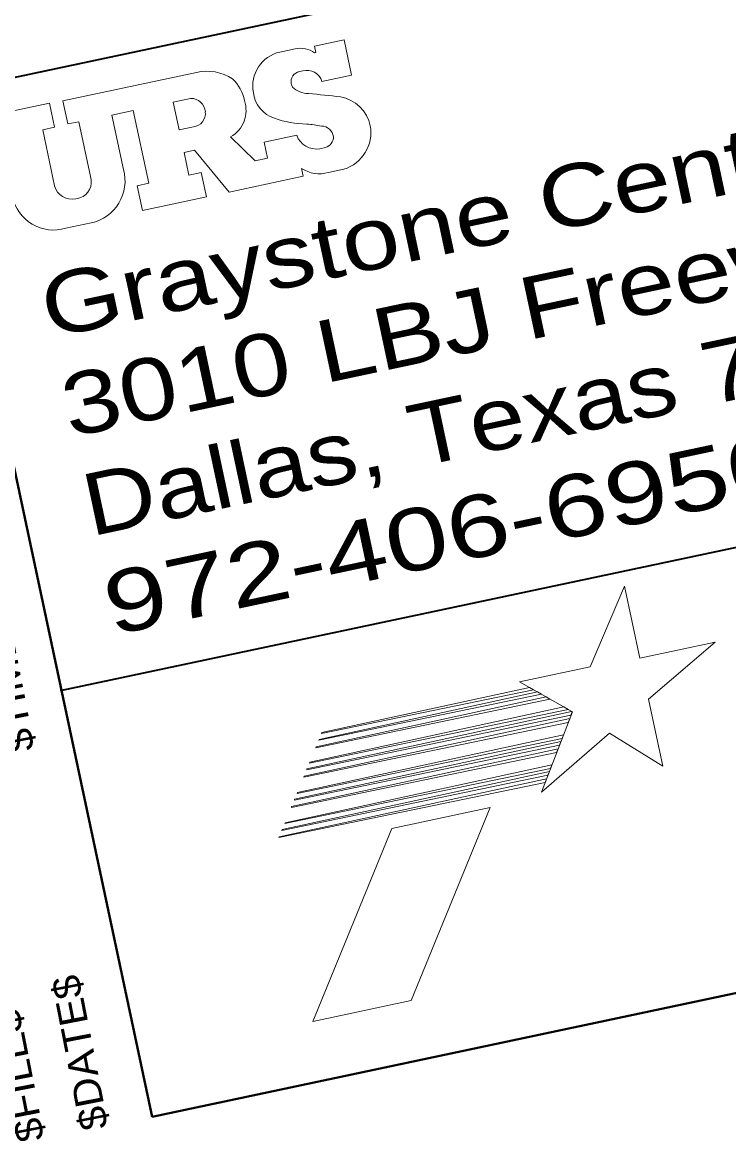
# Model space of a CAD drawing. Extents: x 2357218 to 2371708, y 6973728 to 6980157.
# Drawn here: x 2358089.1 to 2358239.3, y 6973921.3 to 6974159.6 of the extents above; entities that cross this region are included whole.
import ezdxf

# ---------------------------------------------------------------- set-up
doc = ezdxf.new("R2010")
doc.units = 0
doc.header["$LTSCALE"] = 2
for name, color, linetype, lineweight in [('44', 7, 'Continuous', 13), ('62', 7, 'Continuous', 13), ('63', 7, 'Continuous', 13)]:
    doc.layers.add(name, color=color, linetype=linetype, lineweight=lineweight)
doc.layers.add('60', color=7, linetype='Continuous')

msp = doc.modelspace()

# ---------------------------------------------------------------- linework, layer by layer
at = {"layer": '44', "lineweight": 40}
msp.add_lwpolyline([(2358116.692, 6973926.537), (2357409.76, 6977252.388), (2370517.53, 6980038.532)], dxfattribs=at)
at = {"layer": '62', "lineweight": 40}
msp.add_line((2371224.464, 6976712.679), (2358116.692, 6973926.537), dxfattribs=at)
at = {"layer": '62', "lineweight": 35}
for p, q in [((2358706.979, 6974279.557), (2358070.155, 6974144.195)), ((2358484.341, 6974099.558), (2358097.137, 6974017.255))]:
    msp.add_line(p, q, dxfattribs=at)
at = {"layer": '62'}
for p, q in [((2358143.877, 6974153.276), (2358147.138, 6974153.969)), ((2358148.729, 6974149.271), (2358148.058, 6974149.129)), ((2358121.18, 6974142.621), (2358124.862, 6974143.404)), ((2358152.367, 6974132.696), (2358153.533, 6974132.985)), ((2358157.428, 6974128.323), (2358154.166, 6974127.63)), ((2358100.481, 6974122.05), (2358101.323, 6974122.229)), ((2358103.731, 6974116.906), (2358098.3, 6974115.755))]:
    msp.add_line(p, q, dxfattribs=at)
for points in [[(2358151.251, 6974153.118), (2358151.487, 6974153.168), (2358151.203, 6974154.504), (2358157.516, 6974155.845), (2358159.104, 6974148.372), (2358152.792, 6974147.03)], [(2358103.546, 6974126.772), (2358101.062, 6974138.455), (2358098.748, 6974137.963), (2358097.696, 6974142.91), (2358126.103, 6974148.948)], [(2358086.974, 6974122.479), (2358084.356, 6974134.794), (2358081.831, 6974134.257), (2358080.735, 6974139.415), (2358094.833, 6974142.412), (2358095.93, 6974137.254), (2358093.405, 6974136.717), (2358095.933, 6974124.823)], [(2358125.484, 6974137.375), (2358122.433, 6974136.727), (2358121.18, 6974142.621)], [(2358148.481, 6974128.512), (2358148.839, 6974126.828), (2358133.057, 6974123.473), (2358125.671, 6974132.355), (2358123.462, 6974131.885), (2358124.491, 6974127.043), (2358127.121, 6974127.602), (2358128.218, 6974122.445), (2358114.646, 6974119.56), (2358113.527, 6974124.823), (2358115.947, 6974125.337), (2358112.658, 6974140.81), (2358108.134, 6974139.848), (2358110.595, 6974128.27)], [(2358133.369, 6974135.222), (2358138.567, 6974130.145), (2358141.197, 6974130.704), (2358140.481, 6974134.072), (2358147.425, 6974135.548)]]:
    msp.add_lwpolyline(points, dxfattribs=at)
for points in [[(2358217.144, 6974039.586), (2358209.86, 6974022.366), (2358194.85, 6974019.173), (2358206.065, 6974012.808), (2358199.488, 6973995.718), (2358213.939, 6974008.284), (2358225.303, 6974001.204), (2358222.258, 6974015.52), (2358236.459, 6974027.642), (2358220.41, 6974024.223)], [(2358152.793, 6974008.378), (2358196.952, 6974017.967), (2358197.79, 6974017.516), (2358152.736, 6974008.172)], [(2358151.559, 6974005.36), (2358200.468, 6974015.978), (2358201.295, 6974015.505), (2358151.515, 6974005.169)], [(2358152.202, 6974006.924), (2358198.629, 6974017.025), (2358199.47, 6974016.537), (2358152.116, 6974006.737)], [(2358149.618, 6974000.63), (2358205.869, 6974012.891), (2358206.052, 6974012.804), (2358205.773, 6974012.085), (2358149.563, 6974000.416)], [(2358150.222, 6974002.071), (2358204.234, 6974013.842), (2358205.17, 6974013.293), (2358150.158, 6974001.867)], [(2358149.001, 6973999.067), (2358205.512, 6974011.36), (2358205.184, 6974010.523), (2358148.961, 6973998.872)], [(2358146.971, 6973994.186), (2358203.624, 6974006.483), (2358203.326, 6974005.699), (2358146.929, 6973993.994)], [(2358147.583, 6973995.628), (2358204.189, 6974007.919), (2358203.878, 6974007.116), (2358147.515, 6973995.438)], [(2358146.357, 6973992.639), (2358203.027, 6974004.939), (2358202.718, 6974004.143), (2358146.296, 6973992.428)], [(2358144.944, 6973989.189), (2358201.718, 6974001.526), (2358201.419, 6974000.767), (2358144.877, 6973988.993)], [(2358143.726, 6973986.199), (2358200.567, 6973998.55), (2358200.261, 6973997.786), (2358143.645, 6973986.018)], [(2358144.333, 6973987.77), (2358201.171, 6974000.092), (2358200.875, 6973999.342), (2358144.277, 6973987.559)], [(2358167.64, 6973987.976), (2358150.839, 6973946.861), (2358171.775, 6973951.311), (2358188.562, 6973992.429)]]:
    msp.add_lwpolyline(points, close=True, dxfattribs=at)
for centre, radius, start, end in [((2358148.231, 6974148.888), 5.198, 54.47521, 102.13887), ((2358145.45, 6974146.076), 7.37, 102.32723, 191.15289), ((2358128.305, 6974138.996), 10.193, 57.4181, 102.47644), ((2358148.406, 6974146.989), 2.168, 99.22466, 192.15024), ((2358149.606, 6974146.058), 3.331, 16.97622, 105.26327), ((2358128.131, 6974141.519), 8.299, 9.96198, 46.96983), ((2358147.947, 6974146.657), 1.665, 184.31019, 211.43935), ((2358144.74, 6974145.401), 6.564, 186.56461, 251.65547), ((2358150.111, 6974149.816), 5.392, 228.33024, 267.8676), ((2358135.649, 6973969.052), 175.955, 83.11463, 85.35109), ((2358124.907, 6974140.307), 3.097, 3.97357, 90.82265), ((2358130.159, 6974140.864), 6.491, 299.63423, 18.78306), ((2358155.263, 6974135.864), 8.012, 12.4748, 79.35646), ((2358125.182, 6974140.193), 2.833, 276.11318, 6.67154), ((2358149.986, 6974160.437), 22.489, 251.02735, 268.92656), ((2358147.386, 6974110.354), 27.684, 78.98519, 85.48674), ((2358152.61, 6974134.859), 2.67, 8.42761, 88.58816), ((2358154.992, 6974136.172), 8.218, 287.23994, 9.97211), ((2358151.625, 6974137.118), 4.484, 200.49107, 279.52171), ((2358153.006, 6974135.168), 2.246, 283.56527, 2.09036), ((2358101.77, 6974125.845), 9.152, 282.37291, 15.36393), ((2358152.27, 6974134.17), 6.81, 236.19553, 286.17379), ((2358100.145, 6974125.621), 3.591, 289.15137, 18.69604), ((2358095.733, 6974124.332), 8.952, 191.94291, 286.66556), ((2358099.623, 6974125.759), 3.807, 194.2293, 283.01817)]:
    msp.add_arc(centre, radius, start, end, dxfattribs=at)
at = {"layer": '63', "lineweight": 40}
msp.add_line((2371224.464, 6976712.679), (2358116.692, 6973926.537), dxfattribs=at)
at = {"layer": '63'}
for points in [[(2358217.144, 6974039.586), (2358209.86, 6974022.366), (2358194.85, 6974019.173), (2358206.065, 6974012.808), (2358199.488, 6973995.718), (2358213.939, 6974008.284), (2358225.303, 6974001.204), (2358222.258, 6974015.52), (2358236.459, 6974027.642), (2358220.41, 6974024.223)], [(2358152.793, 6974008.378), (2358196.952, 6974017.967), (2358197.79, 6974017.516), (2358152.736, 6974008.172)], [(2358151.559, 6974005.36), (2358200.468, 6974015.978), (2358201.295, 6974015.505), (2358151.515, 6974005.169)], [(2358152.202, 6974006.924), (2358198.629, 6974017.025), (2358199.47, 6974016.537), (2358152.116, 6974006.737)], [(2358149.618, 6974000.63), (2358205.869, 6974012.891), (2358206.052, 6974012.804), (2358205.773, 6974012.085), (2358149.563, 6974000.416)], [(2358150.222, 6974002.071), (2358204.234, 6974013.842), (2358205.17, 6974013.293), (2358150.158, 6974001.867)], [(2358149.001, 6973999.067), (2358205.512, 6974011.36), (2358205.184, 6974010.523), (2358148.961, 6973998.872)], [(2358146.971, 6973994.186), (2358203.624, 6974006.483), (2358203.326, 6974005.699), (2358146.929, 6973993.994)], [(2358147.583, 6973995.628), (2358204.189, 6974007.919), (2358203.878, 6974007.116), (2358147.515, 6973995.438)], [(2358146.357, 6973992.639), (2358203.027, 6974004.939), (2358202.718, 6974004.143), (2358146.296, 6973992.428)], [(2358144.944, 6973989.189), (2358201.718, 6974001.526), (2358201.419, 6974000.767), (2358144.877, 6973988.993)], [(2358143.726, 6973986.199), (2358200.567, 6973998.55), (2358200.261, 6973997.786), (2358143.645, 6973986.018)], [(2358144.333, 6973987.77), (2358201.171, 6974000.092), (2358200.875, 6973999.342), (2358144.277, 6973987.559)], [(2358167.64, 6973987.976), (2358150.839, 6973946.861), (2358171.775, 6973951.311), (2358188.562, 6973992.429)]]:
    msp.add_lwpolyline(points, close=True, dxfattribs=at)

# ---------------------------------------------------------------- texts
at = {"layer": '60', "width": 1.1}
for s, p in [('$TIME$', (2358091.781, 6974004.863)), ('$DATE$', (2358107.421, 6973924.403)), ('$FILE$', (2358093.857, 6973921.904))]:
    msp.add_text(s, height=6, rotation=101, dxfattribs=at).set_placement(p)
at = {"layer": '62'}
for s, width, p in [('3010 LBJ Freeway, Suite 1300', 1.25, (2358099.138, 6974071.19)), ('Graystone Centre', 1.25, (2358094.657, 6974092.268)), ('Dallas, Texas 75234', 1.2, (2358103.618, 6974050.113)), ('972-406-6950', 1.35, (2358108.098, 6974029.035))]:
    msp.add_text(s, height=13.22, rotation=12, dxfattribs=dict(at, width=width)).set_placement(p)

doc.saveas('drawing.dxf')
